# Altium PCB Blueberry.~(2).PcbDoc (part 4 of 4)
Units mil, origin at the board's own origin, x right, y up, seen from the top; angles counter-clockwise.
Board outline 2559.06 x 2204.72 mil, 6 copper layers (Top Layer, Mid-Layer 1, Mid-Layer 2, Mid-Layer 3, Mid-Layer 4, Bottom Layer); 211 components, 214 nets, 1171 pads, 598 vias.
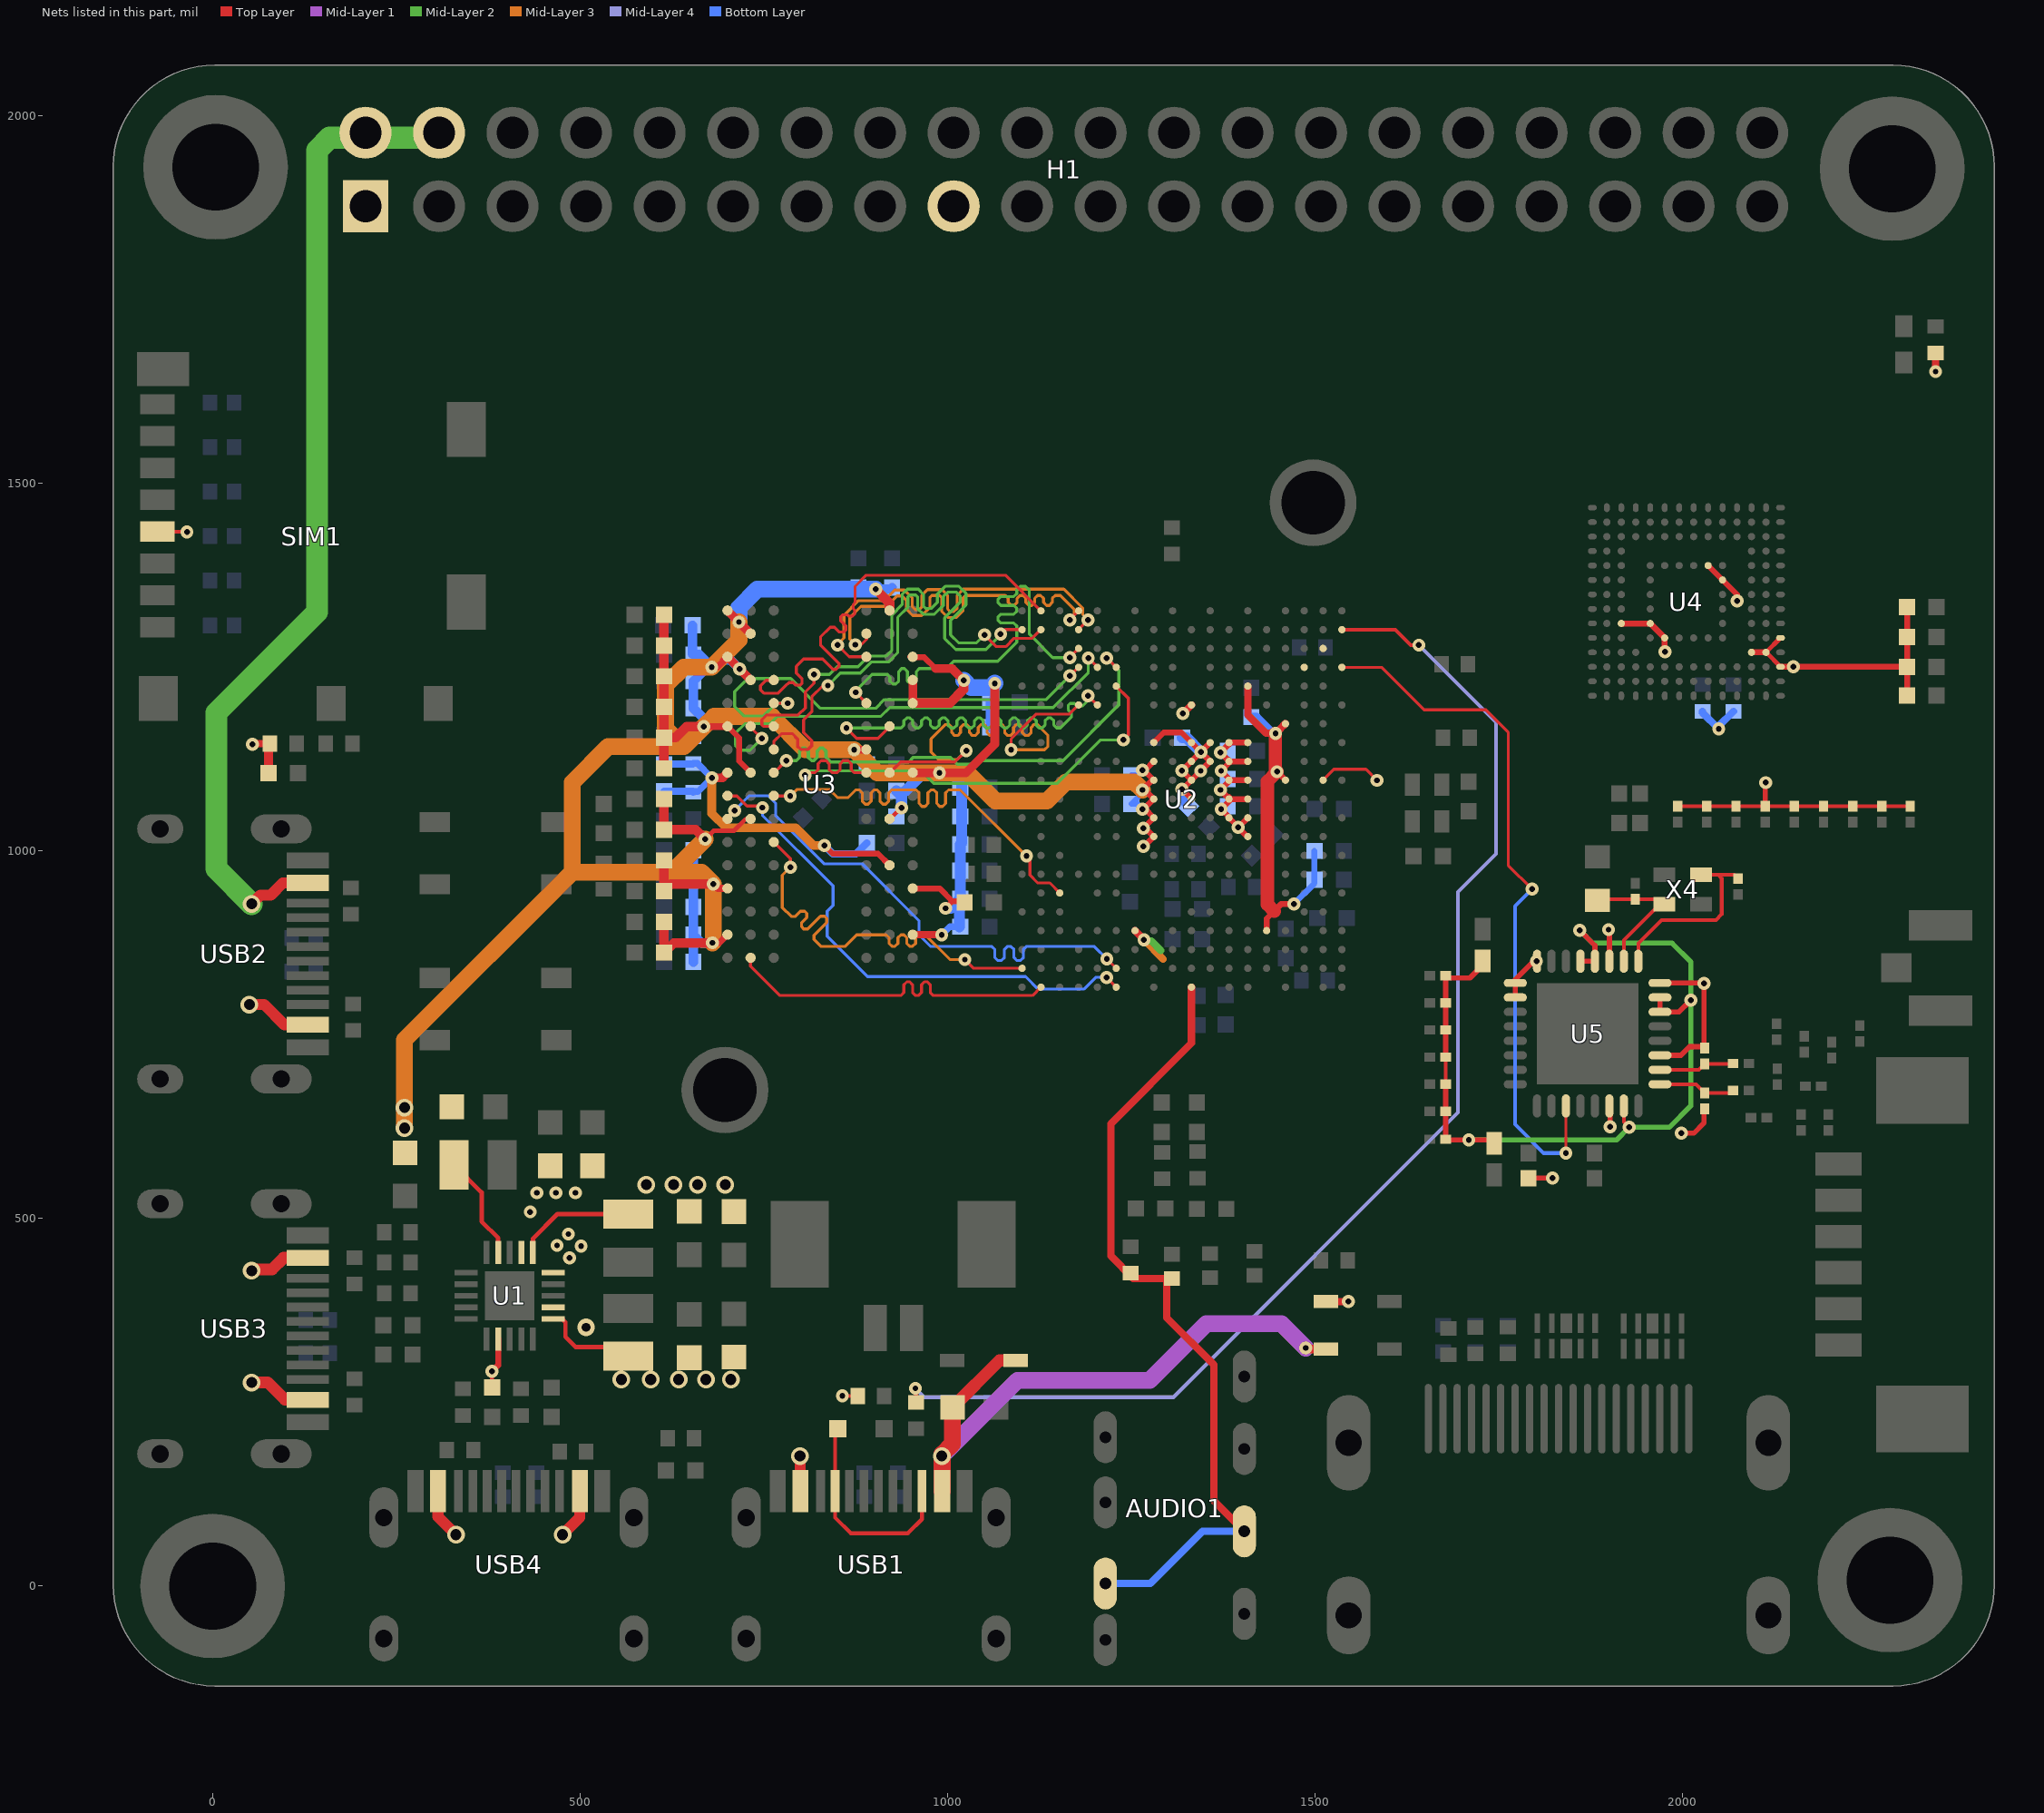
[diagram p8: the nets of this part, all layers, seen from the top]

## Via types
v1: diameter 17.7, hole 7.9, Top Layer to Bottom Layer, 439 vias
v2: diameter 18, hole 8, Top Layer to Bottom Layer, 138 vias
v3: diameter 24, hole 15, Top Layer to Bottom Layer, 19 vias
v4: diameter 24, hole 12, Top Layer to Bottom Layer, 2 vias

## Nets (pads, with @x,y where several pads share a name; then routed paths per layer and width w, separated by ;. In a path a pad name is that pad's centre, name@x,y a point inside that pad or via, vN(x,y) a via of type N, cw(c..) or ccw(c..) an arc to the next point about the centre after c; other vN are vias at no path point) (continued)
SDQ10: U2.P4 U3.F2 | length 635.8
  Top Layer w4: U3.F2@732.04,1169.45 732.04,1167.96 v1(747,1153) ; v1(1191.27,1262.31) U2.P4@1203.67,1249.91
  Mid-Layer 2 w4: v1(747,1153) 731,1137 718,1137 711,1144 711,1160 724,1173 758,1173 768,1183 909,1183 921,1195 1143.46,1195 1191.27,1242.8 v1(1191.27,1262.31)
SDQ11: U2.R4 U3.E3 | length 641.4
  Top Layer w4: U3.E3@760.46,1200.94 v1(782.18,1200.94) ; v1(1166.39,1238.22) U2.R4@1178.08,1249.91
  Mid-Layer 2 w4: v1(782.18,1200.94) 766.68,1200.94 749.27,1183.53 723.27,1183.53 710.27,1196.53 710.27,1216.53 728.27,1234.53 786.47,1234.53 827,1194 902,1194 914,1206 1134.17,1206 v1(1166.39,1238.22)
SDQ12: U2.R6 U3.H8 | length 660.9
  Top Layer w4: U3.H8@921.19,1106.21 935.98,1121 1009.73,1121 v1(1025.27,1136.53) ; v1(1086.27,1137.53) 1086.27,1152.22 1120.27,1186.22 1165.57,1186.22 U2.R6@1178.08,1198.73
  Mid-Layer 3 w4: v1(1025.27,1136.53) 1013.27,1124.53 987.27,1124.53 977.27,1134.53 977.27,1152.22 997.05,1172 1001.53,1172 1005.53,1168 1005.53,1161 1009.53,1157 1013.53,1157 1017.53,1161 1017.53,1168 1021.53,1172 1025.53,1172 1029.53,1168 1029.53,1161 1033.53,1157 1037.53,1157 1041.53,1161 1041.53,1168 1045.53,1172 1049.53,1172 1053.53,1168 1053.53,1161 1057.53,1157 1061.53,1157 1065.53,1161 1065.53,1168 1069.53,1172 1073.53,1172 1077.53,1168 1077.53,1161 1081.53,1157 1085.53,1157 1089.53,1161 1089.53,1168 1093.53,1172 1097.53,1172 1101.53,1168 1101.53,1161 1105.53,1157 1109.53,1157 1113.53,1161 1113.53,1168 1117.53,1172 1121.8,1172 1136.27,1157.53 1136.27,1142.03 1131.77,1137.53 v1(1086.27,1137.53)
  other v1: 1086.27,1137.53
SDQ13: U2.N4 U3.H3 | length 652.7
  Top Layer w4.5: U3.H3@763.71,1106.21 v1(780.27,1122.77) ; v1(1216.27,1262.22) 1216.94,1262.22 U2.N4@1229.26,1249.91
  Mid-Layer 2 w4.5: v1(780.27,1122.77) 793.91,1122.77 798.41,1127.27 798.41,1135.5 802.91,1140 805.91,1140 810.41,1135.5 810.41,1127.27 814.91,1122.77 817.91,1122.77 822.41,1127.27 822.41,1135.5 826.91,1140 829.91,1140 834.41,1135.5 834.41,1127.27 840.68,1121 947,1121 953,1127 1004,1127 1013,1118 1034,1118 1038.77,1122.77 1156.77,1122.77 1233,1199 1233,1245.48 v1(1216.27,1262.22)
  other v1: 1216.27,1262.22
SDQ14: U2.P6 U3.F8 | length 620.7
  Top Layer w4: v1(862.27,1167.22) 876.27,1153.22 905.2,1153.22 U3.F8@921.19,1169.2 ; v1(1190.73,1211.08) 1203.08,1198.73 U2.P6@1203.67,1198.73
  Mid-Layer 2 w4: v1(862.27,1167.22) 936.42,1167.22 940.42,1171.22 940.42,1177 944.42,1181 948.42,1181 952.42,1177 952.42,1171.22 956.42,1167.22 960.42,1167.22 964.42,1171.22 964.42,1177 968.42,1181 972.42,1181 976.42,1177 976.42,1171.22 980.42,1167.22 984.42,1167.22 988.42,1171.22 988.42,1177 992.42,1181 996.42,1181 1000.42,1177 1000.42,1171.22 1004.42,1167.22 1008.42,1167.22 1012.42,1171.22 1012.42,1177 1016.42,1181 1020.42,1181 1024.42,1177 1024.42,1171.22 1028.42,1167.22 1032.42,1167.22 1036.42,1171.22 1036.42,1177 1040.42,1181 1044.42,1181 1048.42,1177 1048.42,1171.22 1052.42,1167.22 1056.42,1167.22 1060.42,1171.22 1060.42,1177 1064.42,1181 1068.42,1181 1072.42,1177 1072.42,1171.22 1076.42,1167.22 1080.42,1167.22 1084.42,1171.22 1084.42,1177 1088.42,1181 1092.42,1181 1096.42,1177 1096.42,1171.22 1100.42,1167.22 1104.42,1167.22 1108.42,1171.22 1108.42,1177 1112.42,1181 1116.42,1181 1120.42,1177 1120.42,1171.22 1124.42,1167.22 1128.42,1167.22 1132.42,1171.22 1132.42,1177 1136.42,1181 1140.42,1181 1144.42,1177 1144.42,1171.22 1148.42,1167.22 1153.22,1167.22 1168.19,1182.19 1168.19,1187.85 1163.9,1192.14 1163.9,1197.79 1166.73,1200.62 1172.38,1200.62 1175.89,1197.12 1183.12,1197.12 1191.62,1205.62 v1@1191.62,1209.82
SDQ15: U2.N5 U3.H7 | length 681
  Top Layer w4: v1(806,1103) 809.58,1106.58 819.69,1106.58 823.69,1110.58 823.69,1118.77 827.69,1122.77 834.69,1122.77 838.69,1118.77 838.69,1110.58 842.69,1106.58 849.69,1106.58 853.69,1110.58 853.69,1118.77 857.69,1122.77 864.69,1122.77 868.69,1118.77 868.69,1110.58 872.69,1106.58 U3.H7@889.37,1106.58
  Top Layer w4.5: U2.N5@1229.2,1224.22 1246,1207.41 1246,1158 v1(1239,1151)
  Mid-Layer 2 w4: v1(806,1103) 812,1109 964,1109 981.14,1091.86 1148.86,1091.86 1208,1151 v1(1239,1151)
  other v1: 806,1103
SDQM0: U2.U1 U3.D3 | length 648.5
  Top Layer w4: U3.D3@763.71,1232.19 U3.D3@760.46,1232.19 ; U3.D3@763.71,1232.44 U3.D3@760.46,1232.19 ; U2.U1@1126.9,1326.69 1078.58,1375 889,1375 874,1360 874,1338 871.47,1335.47 871.47,1329.81 873.33,1327.95 873.33,1322.29 870.5,1319.46 864.85,1319.46 862.98,1321.33 857.33,1321.33 854.5,1318.5 854.5,1312.84 861.2,1306.14 861.2,1300.48 858.37,1297.65 852.71,1297.65 846.01,1304.36 840.36,1304.36 827,1291 827,1280 852,1255 852,1251 848,1247 844,1247 830,1261 804,1261 794,1251 794,1241.83 801.83,1234 801.83,1228.34 799,1225.51 793.34,1225.51 789.76,1229.1 784.1,1229.1 779.4,1224.4 779.27,1224.53 769.27,1214.53 749.87,1214.53 745.27,1219.14 745.27,1224.53 752.93,1232.19 U3.D3@760.46,1232.19
SDQM1: U2.R3 U3.E7 | length 646.4
  Top Layer w4: v1(874.71,1215.68) U3.E7@889.69,1200.7 ; v1(1166,1263) 1178.08,1275.08 U2.R3@1178.08,1275.5
  Mid-Layer 2 w4: v1(874.71,1215.68) 874.71,1217.71 897,1240 918,1240 921.26,1236.74 921.26,1231 925.26,1227 929.26,1227 933.26,1231 933.26,1244 937.26,1248 941.26,1248 945.26,1244 945.26,1231 949.26,1227 953.26,1227 957.26,1231 957.26,1244 961.26,1248 998,1248 1008,1258 1068,1258 1094,1284 1094,1306.01 1090,1310.01 1072.28,1310.01 1068.28,1314.01 1068.28,1318.01 1072.28,1322.01 1090,1322.01 1094,1326.01 1094,1330.01 1090,1334.01 1072.28,1334.01 1068.28,1338.01 1068.28,1342.01 1072.28,1346.01 1090,1346.01 1094,1350.01 1094,1355 1099,1360 1106,1360 1111,1355 1111,1295 1143,1263 v1(1166,1263)
  other v1: 874.71,1215.68 1166,1263
SDQS0_N: U2.R1 U3.B7 | length 562.5
  Top Layer w4: v1(874.27,1280.53) 882.27,1280.53 889.69,1287.96 U3.B7@889.69,1295.19 ; v1(1166,1314) 1166,1314.61 U2.R1@1178.08,1326.69
  Mid-Layer 3 w4: v1(874.27,1280.53) 866.77,1288.03 866.77,1317.28 882.02,1332.53 916.67,1332.53 931.14,1347 937.61,1347 943.87,1340.73 943.87,1328.81 952.31,1320.38 964.69,1320.38 975.93,1331.62 975.93,1345.19 978.27,1347.53 988.82,1347.53 991.87,1344.48 991.87,1325.81 1000.15,1317.53 1011.85,1317.53 1020.87,1326.56 1020.87,1344.48 1023.93,1347.53 1078.38,1347.53 1082.38,1343.53 1082.38,1338.01 1086.38,1334.01 1090.38,1334.01 1094.38,1338.01 1094.38,1343.53 1098.38,1347.53 1102.38,1347.53 1106.38,1343.53 1106.38,1338.01 1110.38,1334.01 1114.38,1334.01 1118.38,1338.01 1118.38,1343.53 1122.38,1347.53 1126.38,1347.53 1130.38,1343.53 1130.38,1338.01 1134.38,1334.01 1138.38,1334.01 1142.38,1338.01 1142.38,1343.53 1146.38,1347.53 1153.47,1347.53 1172,1329 1172,1320 v1(1166,1314)
  other v1: 1166,1314
SDQS0_P: U2.R2 U3.C7 | length 562.8
  Top Layer w4: v1(850,1280) 865.92,1264.08 U3.C7@889.37,1264.08 ; U2.R2@1178.02,1300.99 v1(1191,1314)
  Mid-Layer 3 w4: v1(850,1280) 850,1281 858.77,1289.77 858.77,1320.59 878.71,1340.53 913.36,1340.53 927.82,1355 940.92,1355 951.87,1344.05 951.87,1332.13 955.62,1328.38 961.38,1328.38 964.87,1331.87 964.87,1347.79 972.62,1355.53 992.13,1355.53 999.87,1347.79 999.87,1329.13 1003.47,1325.53 1008.53,1325.53 1012.87,1329.87 1012.87,1347.79 1021.08,1356 1158,1356 1183.77,1330.23 1183.77,1321.23 v1(1191,1314)
SDQS1_N: U2.V2 U3.G3 | length 686.2
  Top Layer w4: U3.G3@763.37,1138.08 763.37,1148.63 774.27,1159.53 788.47,1159.53 796,1152 796,1142 800,1138 810,1138 815,1143 815,1150 804,1161 804,1178.12 815.27,1189.39 815.27,1190.17 ; 815.27,1190.53 815.27,1209.75 830.52,1225 v1(837,1225) ; v1(1072,1295) 1078.09,1301.09 U2.V2@1101.31,1301.09
  Mid-Layer 2 w4: v1(837,1225) 854,1242 881,1242 896,1257 919.31,1257 932,1269.69 932,1317.69 946,1331.69 946,1345.69 948.31,1348 956.69,1348 959,1345.69 959,1329.69 966.69,1322 982,1322 994,1334 994,1346 1000,1352 1012,1352 1017,1347 1017,1338 996,1317 996,1289 1011,1274 1052,1274 1072,1294 v1(1072,1295)
SDQS1_P: U2.U2 U3.F3 | length 687.6
  Top Layer w4: U3.F3@763.32,1169.53 749.27,1169.53 747.27,1171.53 747.27,1178.53 753.73,1185 796.73,1185 806.27,1194.53 806.27,1216.31 818,1228.04 v1(818,1240) ; v1(1050,1294) 1066,1278 1079,1278 1090.22,1289.22 1115.03,1289.22 U2.U2@1126.9,1301.09
  Mid-Layer 2 w4: v1(818,1240) 839,1240 849.5,1250.5 877.89,1250.5 892.39,1265 916,1265 924,1273 924,1321 938,1335 938,1349 945,1356 960,1356 967,1349 967,1333 970,1330 978,1330 986,1338 986,1349.31 996.69,1360 1015.31,1360 1025,1350.31 1025,1334.69 1004,1313.69 1004,1294 1015,1283 1039,1283 v1(1050,1294)
SODT0: U2.N20 U3.K1 | length 718.7
  Top Layer w4: U3.K1@700.72,1043.22 710,1052.5 v1(710,1055) ; v1(1216.5,853.22) U2.N20@1229.26,840.47
  Bottom Layer w4: v1(710,1055) 730,1075 756,1075 766,1065 766,1048 831.47,982.53 883.47,982.53 961,905 961,886 977,870 1060.08,870 1064.08,866 1064.08,855 1068.08,851 1073.08,851 1077.08,855 1077.08,866 1081.08,870 1086.08,870 1090.08,866 1090.08,855 1094.08,851 1099.08,851 1103.08,855 1103.08,866 1107.08,870 1199.72,870 v1(1216.5,853.22)
  other v1: 710,1055
SODT1: U2.N21 U3.J1 | length 707.5
  Top Layer w4: U3.J1@700.72,1074.71 713.29,1074.71 727,1061 746,1061 v1(748,1059) ; v1(1216,828) 1215.9,828.1 1215.9,828.22 U2.N21@1229.26,814.87
  Bottom Layer w4: v1(748,1059) 748,1048.51 844,952.51 844,926 836,918 836,884 891,829 1106,829 1123,812 1185.15,812 1201.15,828 v1(1216,828)
SRAS: U2.T16 U3.J3 | length 601.8
  Top Layer w4: U3.J3@763.71,1074.71 v1(785.77,1074.71) ; v1(1107.27,993.22) 1111.75,988.74 1111.75,967.05 1122.27,956.53 1138.78,956.53 U2.T16@1152.49,942.83
  Mid-Layer 3 w4: v1(785.77,1074.71) 794.59,1083.53 839.27,1083.53 850.27,1072.53 864.53,1072.53 875,1083 879.77,1083 883.77,1079 883.77,1067.67 887.77,1063.67 891.77,1063.67 895.77,1067.67 895.77,1079 899.77,1083 903.77,1083 907.77,1079 907.77,1067.67 911.77,1063.67 915.77,1063.67 919.77,1067.67 919.77,1079 923.77,1083 957.11,1083 961.11,1079 961.11,1064.53 965.11,1060.53 969.11,1060.53 973.11,1064.53 973.11,1079 977.11,1083 981.11,1083 985.11,1079 985.11,1064.53 989.11,1060.53 993.11,1060.53 997.11,1064.53 997.11,1079 1001.11,1083 1017,1083 1106.78,993.22 v1(1107.27,993.22)
  other v1: 785.77,1074.71
SRST: U2.U21 U3.T2 | length 483.5
  Top Layer w4: U3.T2@731.87,854.58 731.87,843.13 771.64,803.36 936.29,803.36 940.29,807.36 940.29,818 944.29,822 948.29,822 952.29,818 952.29,807.36 956.29,803.36 960.29,803.36 964.29,807.36 964.29,818 968.29,822 972.29,822 976.29,818 976.29,807.36 980.29,803.36 1115.39,803.36 U2.U21@1126.9,814.87
SVREF: C58.2 C59.2 C60.2 R10.1 R11.2 U3.H1 U3.M8 | length 560.4
  Top Layer w8: v1(832.27,1007.53) 843.58,996.22 905.2,996.22 U3.M8@920.87,980.58
  Top Layer w12: v1(679.06,1099.53) 694.04,1099.53 U3.H1@700.72,1106.21
  Mid-Layer 3 w12: v1(679.06,1099.53) 679.06,1050.94 698.47,1031.53 793.27,1031.53 817.27,1007.53 v1(832.27,1007.53)
  Bottom Layer w9: R11.2@653,1081.01 660.53,1081.01 v1(679.06,1099.53) 659.59,1119 R10.1@654,1119
  Bottom Layer w10: C60.2@614,1081.01 653,1081.01 R11.2@654,1080 ; C59.2@614,1117.99 653,1117.99 R10.1@654,1119 ; v1(832.27,1007.53) 843.8,996 874.99,996 C58.2@889.99,1011
SWE: U2.V20 U3.L3 | length 602.6
  Top Layer w4: U3.L3@763.71,1011.72 786,989.43 v1(786,978) ; v1(1023.27,852.22) 1035.12,840.37 U2.V20@1101.25,840.37
  Mid-Layer 3 w4: v1(786,978) 775,967 775,923 787.06,910.94 792.72,910.94 799.75,917.97 805.4,917.97 808.23,915.14 808.23,909.49 801.2,902.46 801.2,896.8 804.03,893.97 809.69,893.97 826.91,911.19 832.57,911.19 835.39,908.37 835.39,902.71 818.17,885.49 818.17,879.83 ; 818.23,879.77 828,870 860,870 876,886 916.29,886 920.29,882 920.29,874.16 924.29,870.16 928.29,870.16 932.29,874.16 932.29,882 936.29,886 940.29,886 944.29,882 944.29,874.16 948.29,870.16 952.29,870.16 956.29,874.16 956.29,882 960.29,886 969.27,886 1003.05,852.22 v1(1023.27,852.22)
  other v1: 1023.27,852.22
TV_OUT: AUDIO1.4 AUDIO1.7 D12.2 R30.2 U2.J21 | length 1105.9
  Top Layer w10: U2.J21@1331.57,814.77 1331.57,738.57 1222,629 1222,449 1252.4,418.6 1298,418.6 1298,365 1362,301 1362,116 AUDIO1.4@1403.5,74.5
  Bottom Layer w10: AUDIO1.7@1214.5,3.6 1275.6,3.6 1346.5,74.5 AUDIO1.4@1403.5,74.5
TXPA_ON: C109.2 L5.1 U5.2 | length 102.9
  Top Layer w5: U5.2@1969.08,702.32 2021.93,702.32 L5.1@2029.84,710.23 2067.65,710.23 C109.2@2068.41,711
TXPA_OP: C123.2 L4.1 U5.1 | length 105.6
  Top Layer w5: U5.1@1969.08,682.64 2018,682.64 L4.1@2029.84,670.8 2065.21,670.8 C123.2@2068.41,674
UART1_CTS: U2.B3
UART1_RTS: U2.C4
UART1_TX: U2.A4 U5.27 | length 974.4
  Top Layer w4: U2.A4@1536.29,1249.81 1590.19,1249.81 1648,1192 1732,1192 1762.5,1161.5 1762.5,980.5 v1(1795,948) ; v1@1835.47,589.04 v1(1841,589) 1841.13,589.13 U5.27@1841.13,653.11
  Bottom Layer w5: v1(1795,948) 1771.75,924.75 1771.75,628.19 1810.94,589 v1(1841,589)
USB0_ID: D20.2 USB1.A5 USB1.B5 | length 295.5
  Top Layer w5: USB1.A5@846.8,129.3 846.8,210.3 D20.2@850.5,214
  Top Layer w5.4: USB1.A5@846.8,129.3 846.8,93.2 868,72 946,72 965,91 965,129.2 USB1.B5@964.9,129.3
USB_ID: R34.1 U2.A2 | length 1737.1
  Top Layer w5: v1(956,269) 957,268 R34.1@957,250 ; U2.A2@1536.29,1300.99 1609.01,1300.99 1630,1280 v1(1641,1280)
  Mid-Layer 4 w5: v1(956,269) 968,257 1307,257 1694,644 1694,944 1746,996 1746,1175 v1(1641,1280)
VBUS: C2.1 C7.1 C10.1 D1.2 D22.2 H1.2 H1.4 U1.2 U1.17 U1.20 USB1.A4B9 USB1.B4A9 USB2.A4B9 USB2.B4A9 USB3.A4B9 USB3.B4A9 USB4.A4B9 USB4.B4A9 | length 2656.4
  Top Layer w12: v1(1487,324) 1488.5,322.5 D22.2@1514.8,322.5
  Top Layer w15: v3(50,791) 70,791 97.5,763.5 USB2.B4A9@129.3,763.5 ; v3(53,928) 65,940 79,940 95.5,956.5 USB2.A4B9@129.3,956.5 ; USB4.A4B9@306.5,129.3 306.5,94.5 v3(331,70) ; v3(476,70) 499.5,93.5 USB4.B4A9@499.5,129.3 ; v3(799,177) 799.5,176.5 USB1.A4B9@799.5,129.3 ; v3(992,177) v3@992.5,176.5
  Top Layer w16: v3(53,277) 75,277 98.5,253.5 USB3.B4A9@129.3,253.5 ; v3(53,429) 55,431 81,431 96.5,446.5 USB3.A4B9@129.3,446.5
  Top Layer w17: C2.1@1006.47,243 1070.47,307 D1.2@1092.2,307
  Top Layer w23: USB1.B4A9@992.5,129.3 992.5,176.5 992.5,179.5 1006.47,193.47 C2.1@1006.47,243
  Mid-Layer 1 w23: v3(992,177) 1095,280 1275,280 1352,357 1454,357 v1(1487,324)
  Mid-Layer 2 w30: v3(53,928) 5,976 5,1188 142,1325 142,1953 159,1970 301,1970 H1.4@308,1977
  other v1: 485.39,446.62 501.16,462.37 468.55,463.45 483.9,478.8 432,509 441,535 467,535 493.53,535
  other v4: 508,352
VCC_DRAM: C11.1 C13.1 C17.2 C18.2 C19.2 C20.2 C30.2 C31.2 C32.2 C33.2 C34.2 C35.2 C36.2 C37.2 C38.2 C39.2 C40.2 C41.2 C42.2 C43.2 C44.2 C45.2 C46.2 C47.2 C48.2 C49.2 C50.2 C51.2 C52.2 C53.2 C54.2 C55.2 C56.2 C57.2 C61.2 C62.2 C63.2 C64.2 C65.2 L3.2 R10.2 U1.4 U2.L9 U2.L10 U2.L11 U2.L12 U2.L13 U3.A1 U3.A8 U3.B2 U3.C1 U3.C9 U3.D2 U3.D9 U3.E9 U3.F1 U3.G7 U3.H2 U3.H9 U3.K2 U3.K8 U3.N1 U3.N9 U3.R1 U3.R9 | length 5269.8
  Top Layer w6: L3.2@328.52,572.92 366,535.44 366,496 388.42,473.58 U1.4@388.42,454.02 ; v1(670,1016) 681.53,1027.53 709.27,1027.53 724.95,1043.22 U3.K2@732.21,1043.22 ; U3.K8@921.19,1043.22 936.5,1058.53 v1(937.27,1058.53) ; U3.C9@948.11,1263.69 U3.C9@952.68,1263.69
  Top Layer w8: U3.F1@700.72,1169.2 716.27,1153.65 716.27,1122.16 U3.H2@732.21,1106.21 ; U3.N9@952.37,949.08 988.92,949.08 1006.5,931.5 ; U3.C9@952.68,1263.69 967.79,1263.69 983.46,1248.02 ; v1(997,922) 1006.5,931.5 ; C32.2@1022.99,930 1021.5,931.5 1006.5,931.5 ; v1(1265,1057) v1@1266.7,1057 ; v1(1265,1110) v1@1266.64,1110 ; v1(1266,1006) 1266.88,1006 U2.L13@1280.38,1019.5 1268.87,1031 v1@1266.29,1031 ; v1(1266,1031) v1@1266.29,1031 ; U2.L9@1280.38,1121.86 1268.52,1110 v1@1266.64,1110 ; v1@1266.29,1031 U2.L12@1280.38,1045.09 1268.46,1057 v1@1266.7,1057 ; v1@1266.64,1110 U2.L10@1280.38,1096.27 1278.27,1096.27 v1(1265,1083) 1268.05,1083 U2.L11@1280.38,1070.68 v1@1266.7,1057
  Top Layer w9: v1(668,1169) 699.79,1169 U3.F1@700.37,1169.58 ; v1(679,1250) 686.29,1250 U3.C1@700.37,1264.08 ; v1(680,875) 689.29,875 U3.R1@700.37,886.08
  Top Layer w10: v1(681,955) 686.92,949.08 U3.N1@700.37,949.08 ; v1(872.75,1137.71) U3.G7@889.69,1137.71 ; U3.R9@952.37,886.08 991.45,886.08 v1(991.79,885.74)
  Top Layer w12: U3.C1@700.72,1263.69 v1(716.79,1247.61) U3.D2@732.21,1232.19 ; U3.A1@700.72,1326.68 v1(716,1311.4) U3.B2@732.21,1295.19 ; U3.H9@952.68,1106.21 v1(988.81,1106.21) 1024.94,1106.21 1064,1145.27 v1(1064,1228) ; U3.E9@952.68,1200.7 952.68,1201.08 U3.D9@952.68,1232.19 ; 983.46,1248.02 1005.98,1248.02 v1(1022,1232)
  Top Layer w13: C54.2@614.01,903.54 C48.2@614.01,861.77 627.24,875 v1(680,875) ; C57.2@614.01,987.08 C50.2@614.01,945.31 623.7,955 v1(681,955) ; C55.2@614.01,1070.62 C56.2@614.01,1028.85 657.15,1028.85 v1(670,1016) ; C49.2@614.01,1112.38 C35.2@614.01,1154.15 ; C53.2@614.01,1321.23 C43.2@614.01,1279.46 C36.2@614.01,1237.69 C42.2@614.01,1195.92 C35.2@614.01,1154.15 ; v1(668,1169) 645,1169 630.15,1154.15 C35.2@614.01,1154.15 ; v1(902,1356) 920.87,1337.13 U3.A8@920.87,1327.08 ; U3.E9@952.37,1201.08 952.68,1201.08 1003.08,1201.08 1022,1220 v1(1022,1232)
  Mid-Layer 3 w23: v3(261,623) v3(261,651) 261,743 489,971 ; v1(670,1016) 625,971 ; v1(680,875) 681,876 v1(681,955) 665,971 625,971 ; v1(716,1311.4) 716,1287 v1(679,1250) 641,1250 616,1225 616,1167 641,1142 ; v1(1265,1083) 1254,1094 1161,1094 1135,1068 1065,1068 1026.79,1106.21 v1(988.81,1106.21) 904.25,1106.21 v1(872.75,1137.71) 806.29,1137.71 761,1183 682,1183 v1(668,1169) 641,1142 ; 489,971 489,1093 538,1142 641,1142 ; 489,971 625,971
  Bottom Layer w8: v1(1265,1057) 1257.99,1064.01 C18.2@1249.97,1064.01 1265,1079.04 v1(1265,1083) 1265,1087.98 C20.2@1249.97,1103.01 1258.01,1103.01 v1(1265,1110)
  Bottom Layer w9: R10.2@654,1155 v1(668,1169) ; C34.2@654.01,1197 668,1183.01 668,1180.01 ; v1(872.75,1137.71) 889.99,1120.47 C41.2@889.99,1118 ; C63.2@930.01,1082 943,1082 ; v1(991.79,885.74) 1003.05,897 C30.2@1015.99,897
  Bottom Layer w13: C46.2@652.99,1307 652.99,1268 C40.2@653.99,1267 662,1267 v1(679,1250) ; C38.2@654.01,849 C61.2@653.99,886 ; C33.2@654.01,1001 C33.2@655,1001 ; v1(668,1169) 668,1180.01 C34.2@654.01,1194 654.01,1197 C64.2@654.01,1231 673.01,1250 v1(679,1250) ; v1(670,1016) C33.2@655,1001 ; v1(680,875) 664.99,875 C61.2@653.99,886 ; v1(681,955) 674,962 C31.2@654,962 ; v1(716.79,1247.61) 704.41,1260 689,1260 v1(679,1250) ; v1@899.85,1358.15 v1(902,1356) 922.11,1356 C51.2@924.27,1358.15 ; C47.2@1057.99,1168 C65.2@1057.99,1202 1064,1208.01 v1(1064,1228) ; C61.2@653.99,886 C37.2@654.01,924 C31.2@654,962 ; C31.2@654,962 654,1000 C33.2@655,1001
  Bottom Layer w15: C63.2@930.01,1082 937.27,1074.74 v1(937.27,1058.53) ; 943,1082 967.21,1106.21 v1(988.81,1106.21) 1012.79,1106.21 1019,1100 1019,1011.01 C52.2@1016.99,1009 C45.2@1016.99,973 C39.2@1016.99,935 C39.2@1015.99,934 ; v1(997,922) 1003.99,922 C39.2@1015.99,934 ; C30.2@1015.99,897 C39.2@1015.99,934
  Bottom Layer w23: v1(716,1311.4) 716,1331 741,1356 v1(902,1356) ; v1(1022,1232) 1032,1222 1058,1222 v1(1064,1228)
VD12D: C66.1 C67.1 C71.2 C102.2 C105.1 C106.1 C118.2 C120.1 L9.1 U5.6 U5.7 U5.12 U5.13 U5.31 | length 1197.7
  Top Layer w5: C105.1@1677.45,682.7 C67.1@1677.45,719.6 ; U5.31@1919.87,653.11 1919.87,631.13 v1(1927,624)
  Top Layer w7: C105.1@1677.45,682.7 C66.1@1677.45,645.8 1677.45,608.9 1679.35,607 v1(1709,607) 1735.77,607 C118.2@1740.47,602.3 ; C67.1@1677.45,719.6 C106.1@1677.45,756.5 C120.1@1677.45,793.4 1677.45,827.31 1710.59,827.31 L9.1@1727.73,844.45 ; v1(1860,892) 1880.5,871.5 U5.12@1880.5,849.96 U5.13@1860.81,849.96 ; U5.7@1969.08,800.75 U5.6@1969.08,781.06 1995.06,781.06 v1(2011,797)
  Mid-Layer 2 w7: v1(1709,607) 1910,607 v1(1927,624) 1981.71,624 2011,653.29 v1(2011,797) 2011,849 1985.35,874.65 1877.35,874.65 v1(1860,892)
VDD33: C3.2 C26.2 C27.2 C28.2 C29.2 C68.2 C69.2 C70.2 C75.2 C76.2 C77.2 C81.2 C104.1 C107.2 C108.1 C116.2 C117.2 C124.1 D23.2 H1.1 H1.17 L4.2 L5.2 R16.1 R33.2 R48.2 R50.1 R51.1 R54.2 SIM1.4 U1.12 U2.D7 U2.D10 U2.E18 U2.F5 U2.J6 U2.M18 U4.C6 U4.E6 U4.F5 U4.J10 U4.K9 U4.M4 U4.N4 U4.P3 U4.P5 U5.3 U5.8 U5.11 U5.16 U5.17 U5.18 U5.30 | length 2356.1
  Top Layer w4: v1(1801,850) U5.16@1801.72,850 ; L5.2@2029,733.67 L5.2@2029.84,732.83
  Top Layer w5: SIM1.4@-75.14,1434.39 -35.39,1434.39 v1(-35,1434) ; v1(856.64,258.71) R33.2@877.63,258.7 ; D23.2@1514.8,387 D23.2@1517.76,387 ; C70.2@1993.08,1060.8 C108.1@2032.78,1060.8 C116.2@2072.49,1060.8 C69.2@2112.19,1060.8 C68.2@2151.89,1060.8 C104.1@2191.6,1060.8 C117.2@2231.3,1060.8 C107.2@2271,1060.8 C124.1@2309.53,1060.8
  Top Layer w6: v1(380,292) 380,270.72 C3.2@380.44,270.28 ; U4.P3@2132.95,1250.41 U4.N4@2113.27,1270.11 U4.P5@2132.94,1289.78
  Top Layer w7: U5.18@1772.23,800.75 U5.17@1772.23,820.43 1772.23,825.23 1796.96,849.96 U5.16@1801.76,849.96 ; R54.2@1789.12,554.96 R54.2@1790.12,554.96 v1(1823,555) ; v1(1899,893) 1900.18,891.82 U5.11@1900.18,849.96 ; U5.30@1900.18,653.11 1901,652.29 v1(1901,625) ; U5.3@1969.08,722.01 1997.51,722.01 2009.17,733.67 2029,733.67 v1(2029,820) 2028.57,820.43 U5.8@1969.08,820.43 ; v1(1998,616) 2015,616 2029,630 2029,649.36 L4.2@2029.84,650.2 ; C69.2@2112.19,1060.8 2112.19,1092.19 v1(2113,1093)
  Top Layer w8: v1(380,292) 388.42,300.42 U1.12@388.42,335.82 ; U2.E18@1433.93,891.55 1433.93,907.93 1444.17,918.17 1454,928 v1(1471,928) ; v1(1448,1107.78) U2.D10@1459.52,1096.27 ; U4.C6@1916.41,1309.47 U4.E6@1955.78,1309.47 U4.F5@1975.48,1289.78 1975.48,1271.53 v1(1976,1271) ; U4.J10@2034.52,1388.22 U4.K9@2054.22,1368.53 2074,1348.74 v1(2074,1340) ; U4.M4@2093.59,1270.11 U4.N4@2113.27,1270.11 ; U4.P3@2132.95,1250.41 v1(2150.59,1250.41) ; v1@2151,1250 v1(2150.59,1250.41) ; C75.2@2305.15,1211.58 C76.2@2305.15,1250.27 ; C81.2@2305.15,1331.64 C77.2@2305.15,1290.95 C76.2@2305.15,1250.27 ; v1(2150.59,1250.41) 2305,1250.41 C76.2@2305.15,1250.27
  Top Layer w10: v1(54,1145) 55,1146 R16.1@78,1146 ; U2.M18@1254.79,891.55 1267,879.33 v1(1267,879) ; v1(1320,1187) U2.J6@1331.57,1198.63 ; U2.F5@1408.34,1224.22 1408.34,1184.66 1433,1160 v1(1446,1160) v1@1452,1166 ; D23.2@1517.76,387 v1(1545,387) ; v1(2344,1652) R48.2@2344,1677.45 ; v1@1452,1166 1459.04,1173.04 U2.D7@1459.52,1173.04 1452.48,1166 v1@1452,1166
  Top Layer w12: C28.2@76.01,1106 76.01,1144.01 R16.1@78,1146
  Top Layer w18: 1444.17,918.17 1435,927.35 1435,1094.78 v1@1446,1105.78 ; v1(1446,1160) v1@1446,1105.78 ; v1(1448,1107.78) v1@1446,1105.78
  Mid-Layer 2 w10: v1(1267,879) 1268.47,877.53 1277.2,877.53 1290.07,864.66
  Mid-Layer 3 w10: v1(1267,879) 1293,853
  Bottom Layer w8: v1(1471,928) 1498.99,955.99 C26.2@1498.99,961 C29.2@1498.99,1000
  Bottom Layer w10: R51.1@2027,1190 2027,1188 v1(2049,1166) 2049,1170 R50.1@2069,1190
  Bottom Layer w12: C27.2@1413,1181.99 1420.05,1181.99 v1@1448,1154.05 ; v1(1446,1160) 1448,1158 v1@1448,1154.05 ; v1(1448,1107.78) v1@1448,1154.05
VDD_CPU: C8.1 C9.1 C24.2 C25.2 L2.2 U1.1 U2.H8 U2.H9 U2.J8 U2.J9 U2.J10 U2.J11 U2.L8 | length 457.6
  Top Layer w6: U1.1@435.62,454.02 435.62,472.62 469,506 563.31,506 L2.2@563.44,505.87
  Top Layer w8: U2.L8@1280.38,1147.45 1293.93,1161 1318.01,1161 U2.J8@1331.57,1147.45 v1(1344.36,1134.65) ; U2.J11@1331.57,1070.68 1331.57,1071.04 v1(1318.77,1083.84) 1319.14,1083.84 U2.J10@1331.57,1096.27 ; U2.H8@1357.16,1147.45 v1(1344.36,1134.65) ; U2.J10@1331.57,1096.27 v1(1344.24,1108.94) U2.H9@1357.16,1121.86 v1(1344.36,1134.65) ; U2.J10@1331.57,1096.27 1331.57,1096.45 v1(1318.77,1109.25) 1318.96,1109.25 U2.J9@1331.57,1121.86 v1(1344.36,1134.65)
  Bottom Layer w15: v1(1318.77,1083.84) 1318.77,1072.23 C24.2@1324.85,1066.15 ; C25.2@1319.01,1154 1325.01,1154 v1(1344.36,1134.65)
  other v3: 590,546 627.07,546 659.8,546 697.35,546
VDD_GPU: C4.1 C6.1 C21.2 C22.2 C23.2 L1.2 U1.16 U2.F8 U2.F9 U2.F10 U2.F11 U2.F12 U2.F13 U2.G8 U2.G9 U2.G10 U2.G11 U2.G12 | length 447.5
  Top Layer w6: U1.16@463.22,363.42 475.58,363.42 480,359 480,339 494,325 550.11,325 L1.2@564.44,310.67
  Top Layer w8: U2.G11@1381.46,1071.97 U2.G11@1382.75,1070.68 ; U2.F13@1408.34,1019.5 1407.5,1019.5 v1(1395,1032) ; U2.F12@1408.34,1045.09 1395.25,1032 v1(1395,1032) ; U2.F11@1408.34,1070.68 U2.G11@1382.75,1070.68 ; U2.F10@1408.34,1096.27 U2.G10@1384.73,1096.27 ; U2.F9@1408.34,1121.86 U2.G9@1384.86,1121.86 ; U2.F8@1408.34,1147.45 U2.G8@1382.75,1147.45 1382.75,1144.75 1381.75,1144.75 v1(1371,1134) 1381.75,1123.25 U2.G9@1382.75,1123.25 ; U2.G11@1382.75,1067.75 1384.21,1069.21 U2.G11@1382.75,1070.68 ; U2.G11@1382.75,1067.75 U2.G11@1382.75,1070.68 ; U2.G11@1382.75,1067.75 v1(1372,1057) 1382.75,1046.25 U2.G12@1382.75,1045.09 1395,1032.83 v1(1395,1032) ; U2.G11@1382.75,1070.68 1382.75,1073.25 1380.75,1073.25 v1(1371,1083) U2.G10@1382.75,1094.75 ; U2.G10@1382.75,1094.75 U2.G10@1382.75,1098.25 ; U2.G10@1382.75,1094.75 1384.27,1096.27 U2.G10@1384.73,1096.27 ; U2.G10@1382.75,1098.25 U2.G10@1384.73,1096.27 ; U2.G10@1382.75,1098.25 v1(1372,1109) U2.G9@1382.75,1119.75 ; U2.G9@1382.75,1119.75 U2.G9@1382.75,1123.25 ; U2.G9@1382.75,1119.75 U2.G9@1384.86,1121.86 ; U2.G9@1382.75,1123.25 1384.14,1121.86 U2.G9@1384.86,1121.86
  other v3: 556,281 596,281 634,281 671,281 705,281
WL_REG_ON: U2.B10 | length 85.6
  Top Layer w4: U2.B10@1510.7,1096.27 1525.43,1111 1569,1111 v1(1584,1096)
XI: C121.1 R53.2 U5.10 X4.3 | length 198.6
  Top Layer w5: R53.2@1884,932.76 1885.53,934.29 C121.1@1935.42,934.29 1968.25,934.29 X4.3@1975,927.54 1968.54,927.54 1919.87,878.87 U5.10@1919.87,849.96
XO: C122.1 U5.9 X4.1 | length 262.7
  Top Layer w5: U5.9@1939.55,849.96 1939.55,874.55 1971,906 2045.16,906 2053,913.84 2053,962.64 2048.1,967.54 ; X4.1@2025,967.54 2048.1,967.54 ; C122.1@2075.43,962.25 2070.15,967.54 2048.1,967.54
pads on no net: HDMIOUT.14 U1.10 U1.14 U2.A8 U2.B2 U2.B8 U2.B9 U2.C3 U2.C11 U2.C16 U2.D1 U2.D14 U2.F4 U2.G2 U2.L18 U2.N7 U2.N10 U2.P7 U2.P9 U2.P10 U2.P12 U2.R9 U2.R12 U2.T5 U2.T6 U2.T7 U2.T9 U2.T11 U2.T12 U2.U5 U2.U8 U2.U9 U2.U10 U2.U11 U2.U12 U2.V8 U2.V10 U4.A1 U4.A2 U4.A7 U4.A8 U4.A9 U4.A10 U4.A11 U4.A12 U4.A13 U4.A14 U4.B1 U4.B7 U4.B8 U4.B9 U4.B10 U4.B11 U4.B12 U4.B13 U4.B14 U4.C1 U4.C3 U4.C5 U4.C7 U4.C8 U4.C9 U4.C10 U4.C11 U4.C12 U4.C13 U4.C14 U4.D1 U4.D2 U4.D3 U4.D4 U4.D12 U4.D13 U4.D14 U4.E1 U4.E2 U4.E3 U4.E5 U4.E8 U4.E9 U4.E10 U4.E12 U4.E13 U4.E14 U4.F1 U4.F2 U4.F3 U4.F10 U4.F12 U4.F13 U4.F14 U4.G1 U4.G2 U4.G3 U4.G10 U4.G12 U4.G13 U4.G14 U4.H1 U4.H2 U4.H3 U4.H12 U4.H13 U4.H14 U4.J1 U4.J2 U4.J3 U4.J12 U4.J13 U4.J14 U4.K1 U4.K2 U4.K3 U4.K6 U4.K7 U4.K10 U4.K12 U4.K13 U4.K14 U4.L1 U4.L2 U4.L3 U4.L12 U4.L13 U4.L14 U4.M1 U4.M2 U4.M3 U4.M7 U4.M8 U4.M9 U4.M10 U4.M11 U4.M12 U4.M13 U4.M14 U4.N1 U4.N3 U4.N6 U4.N7 U4.N8 U4.N9 U4.N10 U4.N11 U4.N12 U4.N13 U4.N14 U4.P1 U4.P2 U4.P7 U4.P8 U4.P9 U4.P10 U4.P11 U4.P12 U4.P13 U4.P14 U5.32 USB1.A8 USB1.B8 USB2.A8 USB2.B8 USB3.A8 USB3.B8 USB4.A8 USB4.B8

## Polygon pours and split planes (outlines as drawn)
GND on Bottom Layer "Bottom Layer-GND 1" (solid, remove dead copper, pour order 4): 1023.77,1410.4 1613.77,1410.4 1613.77,775.2 1023.77,775.2
GND on Bottom Layer "Bottom Layer-GND" (solid, remove dead copper, pour order 1): -364.57,2258.07 2622.43,2258.07 2622.43,-311.93 -364.57,-311.93
GND on Mid-Layer 4 "Inner4-GND 1" (solid, remove dead copper, pour order 12): -316.5,2201 2670.5,2201 2670.5,-369 -316.5,-369
GND on Mid-Layer 4 "Inner4-GND" (solid, remove dead copper, pour order 10): 1023,1387.18 1613,1387.18 1613,751.98 1023,751.98
VBUS on Mid-Layer 4 "Inner4-PS 1" (solid, remove dead copper, pour order 8): -58.42,413.42 -58.42,624 220.46,624 284.46,560 509.31,560 563.44,505.87 563.44,326.44 551,314 474.81,314 463.22,325.59 463.22,426.42 435.62,454.02 351.83,454.02 311.23,413.42
VBUS on Mid-Layer 4 "Inner4-PS" (solid, remove dead copper, pour order 5): 998.35,5 188,5 -58.85,251.85 -58.85,960 194,960 194,316 313,197 997.14,197 1035,160 1035,53.9
GND on Mid-Layer 4 "Inner4-GND 2" (solid, remove dead copper, pour order 13): 1291,851 1208,768 728,768 638,858 638,1286 761,1409 1195,1409 1291,1313
GND on Mid-Layer 1 "Inner1-GND 1" (solid, remove dead copper, pour order 15): 1023.77,1388.28 1613.77,1388.28 1613.77,753.08 1023.77,753.08
GND on Mid-Layer 1 "Inner1-GND" (solid, remove dead copper, pour order 14): -355.09,2247.35 2631.91,2247.35 2631.91,-322.65 -355.09,-322.65
VDD_GPU on Mid-Layer 1 "Inner1-VDD_GPU" (solid, remove dead copper, pour order 9): 538,227.93 690.93,227.93 779,316 1253,316 1710,773 1710,1053 1601,1162 1376,1162 1361,1147 1361,1045 1518,888 1518,806 1168.27,456.27 645.27,456.27 507,318 507,258.93
VDD_CPU on Mid-Layer 1 "Inner1-VDD_CPU" (solid, remove dead copper, pour order 11): 1167.27,465.27 1510,808 1510,886 1354,1042 1354,1143 1342,1155 1302,1155 1278.38,1131.38 1278.38,824.38 1042,588 592,588 565,561 565,502 601.73,465.27
GND on Top Layer "Top Layer-GND" (solid, remove dead copper, pour order 0): -372,2266 2615,2266 2615,-304 -372,-304
VDD33 on Mid-Layer 2 "Inner2-GND" (solid, remove dead copper, pour order 2): -343.3,2234.55 2643.7,2234.55 2643.7,-335.45 -343.3,-335.45
VDD33 on Mid-Layer 3 "Inner3-3V3" (solid, remove dead copper, pour order 3): -330.5,2220.37 2656.5,2220.37 2656.5,-349.63 -330.5,-349.63

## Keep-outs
Top Layer:
  region: 661,1423.68 1558.79,1423.68 1558.79,791 661,791
  region: 1791.62,227.71 1791.62,360.78 1767.4,385 1645,385 1402,628 1402,812.45 1407,817.45 1511.55,817.45 1511.55,693.45 1687,518 1940.27,518 2013.29,444.98 2013.29,232.8 2008.2,227.71
Mid-Layer 2:
  region: 688.5,1270.12 815.72,1397.34 1145.2,1397.34 1271.7,1270.84 1271.7,862.01 1158.35,748.66 800.5,748.66 688.5,860.66
Mid-Layer 3:
  region: 1280.5,888.5 1176.5,784.5 786.5,784.5 639.5,931.5 639.5,1261.5 786.5,1408.5 1176.5,1408.5 1280.5,1304.5
  region: 865.56,1235.41 913.2,1187.77 1097.2,1187.77 1144.2,1234.77 1144.2,1300.77 1111.23,1333.74 918.66,1333.74 865.56,1280.65
  region: 700.37,871.63 771,801 1146.8,801 1227,881.2 1227,948 1133.03,1041.97 781.46,1041.97 700.37,960.88
Bottom Layer:
  region: 736.47,1027.53 786,978 786,945.64 799.64,932 799.64,892.36 894.64,797.36 1219.4,797.36 1236.81,814.77 1236.81,858.5 1210.68,884.63 1003.37,884.63 880.47,1007.53 832.27,1007.53 765.09,1074.71 707.71,1074.71 693,1060 693,1037 702.47,1027.53
  region: 890.21,1294.96 1122.85,1294.96 1145.38,1272.44 1145.38,1233.28 1122.38,1210.28 891.53,1210.28 858.53,1243.28 858.53,1263.28
Keep-Out Layer:
  the board outline again, w10

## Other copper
Top Layer:
  region net VBUS: 447.42,375.22 483.78,375.22 493,366 493,342 498,337 518.17,337 522.44,341.27 522.44,361.56 501,383 447,383 447,375.64 447.42,375.22
  region net 1V8: 431.01,352 430.72,296.28 450,277 450,259 472,259 472,308 440,340 440,352 431.01,352
  region net VCC_DRAM: 348,572.92 348,669 258,669 244,655 244,572.92 348,572.92
  region net VDD_GPU: 530,331 530,278 543,265 713,265 727,279 727,331 530,331
  region net VDD_CPU: 530,486 727,486 727,545.62 709.12,563.5 566.5,563.5 530,527 530,486
  region net NetL1_1: 448,399 595,399 599,395 599,358 536,358 503,391 448,391 448,399
  region net NetL2_1: 447.42,414.62 489.62,414.62 526,451 526,460 599,460 599,411.72 594,406.72 447.42,406.72 447.42,414.62
  region net VBUS: 447.42,422.52 447.42,465.42 473,491 507,491 516,482 516,452 486,422 447.94,422 447.42,422.52
  region net VBUS: 415.92,438.22 415.92,526.92 442,553 442,589 533,589 533,555 493,515 464,515 424,475 424,438 416.14,438 415.92,438.22
  region net NetL3_1: 408.02,438.22 408,438.24 408,534 413,539 413,606 412,607 374,607 374,500 400,474 400,438.44 400.22,438.22 408.02,438.22

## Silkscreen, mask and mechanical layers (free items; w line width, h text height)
Top Overlay:
  text "GPIO" at 155,1738 h69
  text "Embedded Linux development board" at 835.82,1685.97 h70 r359.95
  text "Power" at 2264.63,1635.57 h30 r90
  text "by: aixiao@aixiao.me" at 842.81,1617.27 h57
  text "2023 v1.0" at 842.81,1532.77 h57
  text "eMMC" at 2345.26,1355.74 h69 r90
  text "TF Card" at 442,1185 h69 r90
  text "USB" at -109,1065 h69
  text "DRAM" at 782,717.9 h67.5
  text "USB" at -109,556 h69
  text "FAN" at 759,525 h69
  text "RJ45" at 2160.33,108.01 h69
  text "USB" at 200,-98 h69 r90
  text "OTG" at 693,-98 h69 r90
  text "Audio" at 1169,-98 h69 r90
  text "HDMI" at 1513,-98 h69 r90
Bottom Overlay:
  text "D7" at -35,1591.93 h45
  text "D6" at -36.2,1532.23 h45
  text "D5" at -35,1472.03 h45
  text "D4" at -33.8,1411.33 h45
  text "D3" at -35,1351.63 h45
  text "D2" at -35,1290.93 h45
  text "D13" at 91.64,868.08 h45
  text "D14" at 91.64,824.58 h45
Mechanical 6:
  circle w8: c1495.78,1473.66 r39.37
  lines w6: 604.23,582.11 1588.48,582.11 1588.48,1566.36 604.23,1566.36 604.23,582.11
